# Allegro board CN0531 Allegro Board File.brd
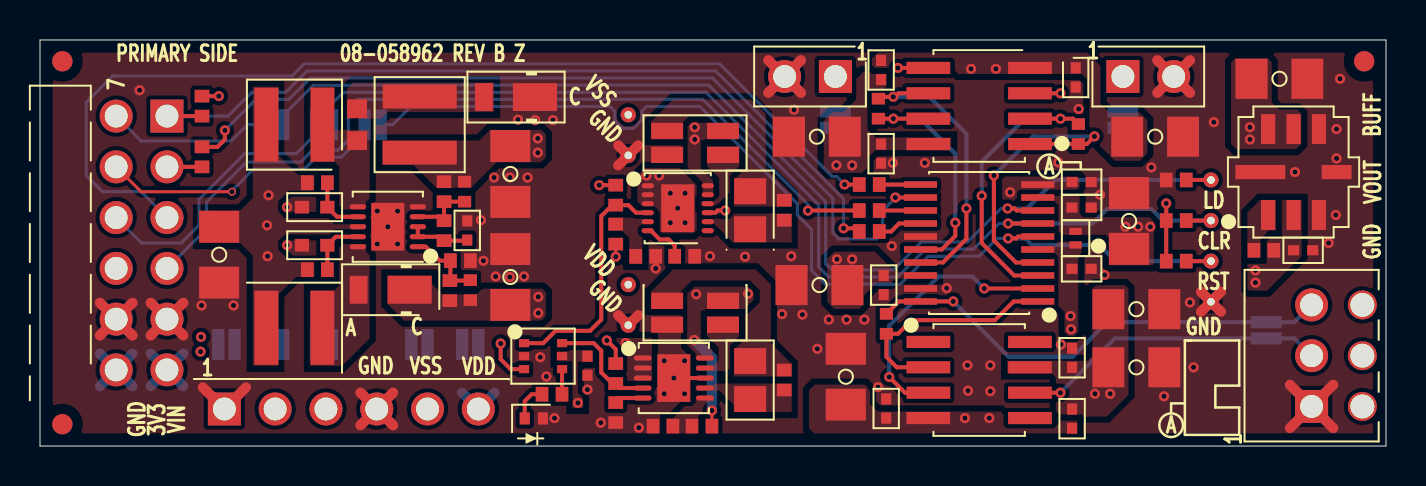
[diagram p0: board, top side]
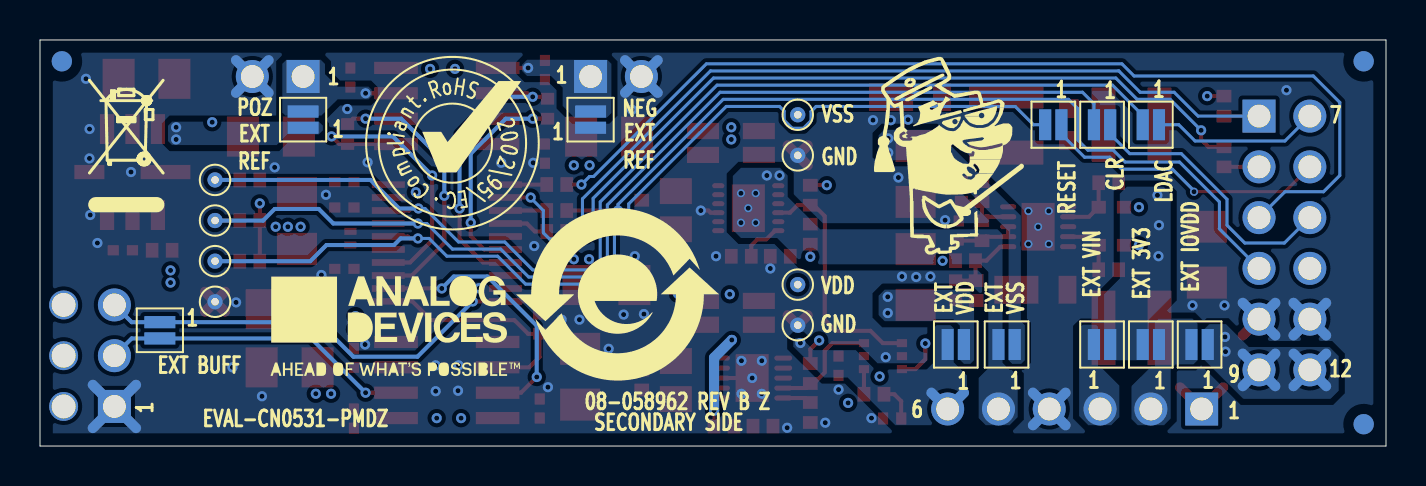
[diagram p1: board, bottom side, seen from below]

Outline 67.31 x 20.32 mm; copper layers: TOP, L2_GND, L3_PWR, BOTTOM. Coordinates in mm from the lower left corner of the outline.
Outline path: 0,20.32 0,0 67.31,0 67.31,20.32 0,20.32

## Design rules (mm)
constraint set DEFAULT: min track width 0.152

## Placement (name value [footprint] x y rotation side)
A1  AD8676BRZ  [SO8]  46.96 17.02 90 top
C1  4.7uF  [C1206_SP]  32.76 6.67 180 top
C2  4.7uF  [C1206_SP]  32.76 15.17 180 top
C3  0.1uF  [C0402H22]  27.38 4.02 90 top
C4  10uF  [C1206H71]  8.96 9.58 270 top
C5  0.1uF  [C0402H22]  63.16 9.8 180 top
C6  10uF  [C1206H71]  61.98 18.38 0 top
C7  10uF  [C1206H71]  38.85 15.48 0 top
C8  10uF  [C1206H71]  55.77 15.48 180 top
C9  0.47uF  [C0402_A]  13.73 10.05 180 top
C10  0.47uF  [C0402_A]  13.73 11.95 180 top
C11  0.1uF  [C0402H22]  42.06 14.63 90 top
C12  0.1uF  [C0402H22]  51.79 18.44 90 top
C13  0.1uF  [C0402H22]  42.06 18.82 90 top
C14  1uF  [C0603]  15.86 16.08 90 top
C15  220pF  [C0402]  51.93 15.61 270 top
C16  220pF  [C0402]  41.93 16.88 90 top
C17  33pF  [C0402]  21.52 7.8 90 top
C18  75pF  [C0402]  21.23 12.73 90 top
C19  4.7uF  [C1206H71]  23.52 8.46 90 top
C20  10uF  [C1206H71]  23.52 13.61 270 top
C21  0.1uF  [C0402H22]  21.37 10.79 90 top
C24  10uF  [C1206H71]  54.46 11.26 270 top
C25  0.1uF  [C0402H22]  52.09 11.94 180 top
C26  0.1uF  [C0402H22]  52.09 13.21 180 top
C27  0.1uF  [C0402H22]  42.19 8.06 270 top
C28  10uF  [C1206H71]  38.98 8.06 180 top
C29  10uF  [C1206H71]  54.83 6.85 0 top
C30  0.1uF  [C0402H22]  52.09 8.87 0 top
C31  10pF  [C0402]  42.33 6.12 270 top
C32  0.1uF  [C0402H22]  51.61 1.37 90 top
C33  0.1uF  [C0402H22]  42.32 1.88 90 top
C34  10uF  [C1206H71]  40.3 3.47 90 top
C35  10uF  [C1206H71]  54.83 3.94 0 top
C36  0.1uF  [C0402H22]  51.61 4.42 90 top
C37  4.7uF  [C0805H53]  35.51 3.3 90 top
C38  4.7uF  [C0805H53]  35.51 11.8 90 top
D1  DFLS120L-7  [POWERDI123]  17.54 7.82 180 top
D2  DFLS120L-7  [POWERDI123]  23.81 17.46 180 top
D3  BAT54LPS  [DFN2_1X0_6]  51.79 10.4 90 top
DS1  SML-P11MTT86RR  [LED0402]  24.7 1.38 180 top
L1  10UH  [LSMSQ157H71-2]  12.73 5.92 0 top
L2  15UH  [LSMSQ157H47_PS]  12.73 16.08 0 top
L3  15UH  [LSMSQ157H47_PS]  18.99 16.08 270 top
NOREF  -  []  67.3 20.32 180 top
NOREF#2  -  []  0 20.32 270 top
NOREF#3  -  []  40.61 255.22 0 top
NOREF#4  -  []  0 0 0 top
NOREF#5  -  []  103.86 66.62 0 top
NOREF#6  -  [unnamed#2]  1.12 19.25 0 top
NOREF#7  -  []  67.31 0 90 top
NOREF#8  -  []  33.88 33.1 0 top
NOREF#9  -  []  67.3 0 90 top
NOREF#10  -  [unnamed#2]  66.22 19.25 0 top
NOREF#11  -  []  3.81 3.81 0 top
NOREF#12  -  []  0 0 0 top
NOREF#13  -  []  28.3 180.8 270 top
NOREF#14  -  []  0 0 0 top
NOREF#15  -  []  -59.21 -127.81 0 top
NOREF#16  -  []  -59.33 -127.81 0 top
NOREF#17  -  []  103.48 -60.38 0 top
NOREF#18  -  []  56.87 139.01 0 top
NOREF#19  -  []  67.31 0 0 top
NOREF#20  -  []  0 20.32 0 top
NOREF#21  -  []  0 20.32 0 top
NOREF#22  -  [unnamed#2]  1.12 1.09 0 top
NOREF#23  -  []  3.81 3.81 0 top
NOREF#24  -  [unnamed#2]  1.12 19.25 180 bottom
NOREF#25  -  []  63.2 11.76 180 bottom
NOREF#26  -  []  21.86 14.53 180 bottom
NOREF#27  -  [unnamed#2]  1.12 1.09 180 bottom
NOREF#28  -  []  46.69 15.16 180 bottom
NOREF#29  -  [unnamed#2]  66.22 19.25 180 bottom
NOREF#30  -  []  49.84 5.97 180 bottom
NOREF#31  -  []  38.43 7.59 180 bottom
P1  TSW-106-07-G-S  [CNHDR1X6H330]  9.22 1.85 0 top
P2  TSW-106-25-F-D-RA  [CNHDRRA2X6H240]  6.35 16.51 270 top
P3  TSW-102-07-G-S  [CNTHMHDR1X2L200W98H343]  54.15 18.49 0 top
P4  TSW-102-07-G-S  [CNTHMHDR1X2L200W98H343]  39.78 18.49 180 top
P5  1725669  [CNTH1X3H335]  63.59 1.98 90 top
P6  -  [JPSLD02]  9.32 5.08 0 bottom
P7  -  [JPSLD02]  11.76 5.08 0 bottom
P8  -  [JPSLD02]  14.2 5.08 180 bottom
P9  -  [JPSLD02]  54.15 16.33 90 bottom
P10  -  [JPSLD02]  39.78 16.33 90 bottom
P11  -  [JPSLD02]  21.51 5.08 0 bottom
P12  -  [JPSLD02]  18.97 5.08 0 bottom
P13  -  [JPSLD02]  61.32 5.79 270 bottom
P14  -  [JPSLD02]  11.76 16.08 0 bottom
P15  -  [JPSLD02]  14.2 16.08 0 bottom
P16  -  [JPSLD02]  16.64 16.08 0 bottom
R1  10K  [R0402]  8.1 17.01 270 top
R2  10K  [R0402]  56.82 9.25 0 top
R3  10K  [R0402]  56.82 11.28 0 top
R4  120  [R0402]  25.61 2.59 180 top
R5  10K  [R0402]  56.82 13.32 180 top
R6  10K  [R0402]  61.2 9.8 180 top
R7  4.7K  [R0402]  13.87 8.82 0 top
R8  4.7K  [R0402]  13.87 13.18 0 top
R9  105K  [R0402]  20.5 7.78 90 top
R10  15K  [R0402]  21.03 9.28 0 top
R11  15K  [R0402]  20.21 10.78 90 top
R12  120K  [R0402]  20.21 12.73 90 top
R13  1MEG  [R0402]  33.1 1 180 top
R14  51K  [R0402]  31.15 1 180 top
R15  1MEG  [R0402]  28.79 10.6 90 top
R16  51K  [R0402]  30.29 9.5 0 top
R17  200K  [R0402]  28.79 3.63 90 top
R18  200K  [R0402]  28.79 12.55 270 top
R19  1.3K  [R0402]  28.79 1.68 270 top
R20  19.6K  [R0402]  32.24 9.5 0 top
R21  75K  [R0402]  37.22 3.3 90 top
R22  75K  [R0402]  37.22 11.8 90 top
R23  0  [R0402]  41.47 10.74 180 top
R24  0  [R0402]  41.47 13.09 180 top
R25  0  [R0402]  8.1 14.47 270 top
R26  0  [R0402]  41.47 11.79 180 top
TP1  TESTPAD  [TPC30D15]  58.56 7.22 0 top
TP2  TESTPAD  [TPC30D15]  58.56 13.32 0 top
TP3  TESTPAD  [TPC30D15]  58.56 11.28 0 top
TP4  TESTPAD  [TPC30D15]  58.56 9.25 0 top
TP5  TESTPAD  [TPC30D15]  29.42 8.08 0 top
TP6  TESTPAD  [TPC30D15]  29.42 16.58 0 top
TP7  TESTPAD  [TPC30D15]  29.42 6.05 0 top
TP8  TESTPAD  [TPC30D15]  29.42 14.54 0 top
U1  NC7SZ11P6X  [SC70-6]  25.16 4.5 270 top
U2  LTC6655BHLS8-5#PBF  [LCC8H61]  62.69 13.71 0 top
U3  LT3471EDD#PBF  [QFN10_3X3_PAD2_38X1_64]  17.39 10.97 90 top
U4  AD5791BRUZ  [TSSOP20]  46.96 10.16 90 top
U5  LT3093EDD#PBF  [DFN12_3X3_PAD2_38X1_65]  31.89 11.9 270 top
U6  LT3042EDD#PBF  [DFN10_3X3_PAD2_38X1_64]  31.7 3.4 270 top
U7  AD8675ARZ  [SO8]  46.96 3.3 270 top

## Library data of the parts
A1 = ADOPAMP2: Tolerance: N/A; User Part Number: UPN; alternate symbols: (); part number: ADOPAMP2_SM-AD8676BRZ,E011141,SO8; tolerance: N/A
C1 C2 = CAP_SP: User Part Number: UPN; Tolerance: 20; alternate symbols: (); part number: CAP_SP_SM-4.7UF,50V,20,E038838,C1206_SP; tolerance: 20
C3 C5 C11-C13 C21 C25-C27 C30 C32 C33 C36 = CAP: Tolerance: 10; User Part Number: UPN; alternate symbols: (); part number: CAP_SM-0.1UF,50V,10,E018452,C0402H22; tolerance: 10
C4 C6-C8 C20 C24 C28 C29 C34 C35 = CAP: Tolerance: 10; User Part Number: UPN; alternate symbols: (); part number: CAP_SM-10UF,50V,10,E026881,C1206H71; tolerance: 10
C9 C10 = CAP: Tolerance: 10; User Part Number: UPN; alternate symbols: (); part number: CAP_SM-0.47UF,50V,10,E020369,C0402_A; tolerance: 10
C14 = CAP: User Part Number: UPN; Tolerance: 10; alternate symbols: (); part number: CAP_SM-1UF,50V,10,E023087,C0603; tolerance: 10
C15 C16 = CAP: User Part Number: UPN; Tolerance: 5; alternate symbols: (); part number: CAP_SM-220PF,50V,5,E018153,C0402; tolerance: 5
C17 = CAP: User Part Number: UPN; Tolerance: 5; alternate symbols: (); part number: CAP_SM-33PF,50V,5,E027128,C0402; tolerance: 5
C18 = CAP: User Part Number: UPN; Tolerance: 5; alternate symbols: (); part number: CAP_SM-75PF,50V,5,E033948,C0402; tolerance: 5
C19 = CAP: Tolerance: 20; User Part Number: UPN; alternate symbols: (); part number: CAP_SM-4.7UF,50V,20,E028522,C1206H71; tolerance: 20
C31 = CAP: User Part Number: UPN; Tolerance: 5; alternate symbols: (); part number: CAP_SM-10PF,50V,5,E035301,C0402; tolerance: 5
C37 C38 = CAP: Tolerance: 10; User Part Number: UPN; alternate symbols: (); part number: CAP_SM-4.7UF,25V,10,E025752,C0805H53; tolerance: 10
D1 D2 = DIOSCHOTTKY: User Part Number: UPN; Tolerance: N/A; alternate symbols: (); part number: DIOSCHOTTKY_SM-DFLS120L-7,20V,N/A,E033687,POWERDI123; tolerance: N/A
D3 = DIOSCHOTTKY: Tolerance: N/A; User Part Number: UPN; alternate symbols: (); part number: DIOSCHOTTKY_SM-BAT54LPS,30V,N/A,E023691,DFN2_1X0_6; tolerance: N/A
DS1 = DIOLED: User Part Number: UPN; Tolerance: N/A; alternate symbols: (); part number: DIOLED_SM-SML-P11MTT86R,N/A,N/A,E014445,LED0402; tolerance: N/A
L1 = IND: User Part Number: UPN; Tolerance: 20; alternate symbols: (); part number: IND_SM-10UH,20,E032200,LSMSQ157H71-2; tolerance: 20
L2 L3 = IND: User Part Number: UPN; Tolerance: 20; alternate symbols: (); part number: IND_SM-15UH,20,E032207,LSMSQ157H47_PS; tolerance: 20
P1 = CN6P: Tolerance: N/A; User Part Number: UPN; alternate symbols: (); part number: CN6P_TH-TSW-106-07-G-S,E026233,CNHDR1X6H330; tolerance: N/A
P2 = CN12P_V3: User Part Number: UPN; Tolerance: N/A; alternate symbols: (); part number: CN12P_V3_TH-TSW-106-25-F-D-RA,E018495,CNHDRRA2X6H240; tolerance: N/A
P3 P4 = CN2P: User Part Number: UPN; Tolerance: N/A; alternate symbols: (); part number: CN2P_TH-TSW-102-07-G-S,E031850,CNTHMHDR1X2L200W98H343; tolerance: N/A
P5 = CN3P: Tolerance: N/A; User Part Number: UPN; alternate symbols: (); part number: CN3P_TH-1725669,E019899,CNTH1X3H335; tolerance: N/A
P6-P16 = NC2P: User Part Number: UPN; Tolerance: N/A; alternate symbols: (); part number: NC2P_SM-JPSLD02,E006230,JPSLD02; tolerance: N/A
R1-R3 R5 R6 = RES: User Part Number: UPN; Tolerance: 1; alternate symbols: (R0402L,R0402L_ALT); part number: RES_SM-10K,E003751,1/10W,1,R0402; tolerance: 1
R4 = RES: User Part Number: UPN; Tolerance: 5; alternate symbols: (R0402L); part number: RES_SM-120,E003453,1/10W,5,R0402; tolerance: 5
R7 R8 = RES: User Part Number: UPN; Tolerance: 1; alternate symbols: (R0402L,R0402L_ALT); part number: RES_SM-4.7K,E008190,1/10W,1,R0402; tolerance: 1
R9 = RES: User Part Number: UPN; Tolerance: 1; alternate symbols: (R0402L); part number: RES_SM-105K,E019614,1/16W,1,R0402; tolerance: 1
R10 R11 = RES: User Part Number: UPN; Tolerance: 1; alternate symbols: (R0402L); part number: RES_SM-15K,E007441,1/10W,1,R0402; tolerance: 1
R12 = RES: User Part Number: UPN; Tolerance: 1; alternate symbols: (R0402L); part number: RES_SM-120K,E015615,1/10W,1,R0402; tolerance: 1
R13 R15 = RES: User Part Number: UPN; Tolerance: 1; alternate symbols: (R0402L); part number: RES_SM-1MEG,E003749,1/10W,1,R0402; tolerance: 1
R14 R16 = RES: User Part Number: UPN; Tolerance: 1; alternate symbols: (R0402L,R0402L_ALT); part number: RES_SM-51K,E013080,1/10W,1,R0402; tolerance: 1
R17 R18 = RES: User Part Number: UPN; Tolerance: 1; alternate symbols: (R0402L); part number: RES_SM-200K,E004033,1/10W,1,R0402; tolerance: 1
R19 = RES: User Part Number: UPN; Tolerance: 1; alternate symbols: (R0402L,R0402L_ALT); part number: RES_SM-1.3K,E015613,1/10W,1,R0402; tolerance: 1
R20 = RES: User Part Number: UPN; Tolerance: 1; alternate symbols: (R0402L); part number: RES_SM-19.6K,E027321,1/10W,1,R0402; tolerance: 1
R21 R22 = RES: User Part Number: UPN; Tolerance: 1; alternate symbols: (R0402L,R0402L_ALT); part number: RES_SM-75K,E011153,1/10W,1,R0402; tolerance: 1
R23-R26 = RES: User Part Number: UPN; Tolerance: JUMPER; alternate symbols: (R0402L,R0402L_ALT); part number: RES_SM-0,E003438,1/10W,JUMPER,R0402; tolerance: JUMPER
TP1-TP8 = NCTESTPAD: Tolerance: N/A; User Part Number: UPN; alternate symbols: (); part number: NCTESTPAD_TH-TESTPAD,E013464,TPC30D15; tolerance: N/A
U1 = ICNC7SZ11X6X: Tolerance: N/A; User Part Number: UPN; alternate symbols: (); part number: ICNC7SZ11X6X_SM-NC7SZ11P6X,E022115,SC70-6; tolerance: N/A
U2 = LINLTC6655_V2: User Part Number: UPN; Tolerance: N/A; alternate symbols: (); part number: LINLTC6655_V2_SM-LTC6655BHLS8-5#PBF,E030760,LCC8H61; tolerance: N/A
U3 = LINLT3471: User Part Number: UPN; Tolerance: N/A; alternate symbols: (); part number: LINLT3471_SM-LT3471EDD#PBF,E030330,QFN10_3X3_PAD2_38X1_64; tolerance: N/A
U4 = AD5791: Tolerance: N/A; User Part Number: UPN; alternate symbols: (); part number: AD5791_SM-AD5791BRUZ,E011635,TSSOP20; tolerance: N/A
U5 = ADLT3093: User Part Number: UPN; Tolerance: N/A; alternate symbols: (); part number: ADLT3093_SM-LT3093EDD#PBF,E038442,DFN12_3X3_PAD2_38X1_65; tolerance: N/A
U6 = LINLT3042: Tolerance: N/A; User Part Number: UPN; alternate symbols: (); part number: LINLT3042_SM-LT3042EDD#PBF,E029807,DFN10_3X3_PAD2_38X1_64; tolerance: N/A
U7 = AD8675: Tolerance: N/A; User Part Number: UPN; alternate symbols: (); part number: AD8675_SM-AD8675ARZ,E005913,SO8; tolerance: N/A

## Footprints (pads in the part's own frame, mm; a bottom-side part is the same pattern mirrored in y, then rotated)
C0402
  rect 0.584x0.66 smd: 1(-0.5,0) 2(0.5,0)
C0402_A
  rect 0.711x0.635 smd: 1(-0.635,0) 2(0.635,0)
C0402H22
  rect 0.559x0.508 smd: 1(-0.479,0) 2(0.479,0)
C0603
  rect 0.94x0.991 smd: 1(-0.8,0) 2(0.8,0)
C0805H53
  rect 1.295x1.6 smd: 1(-0.953,0) 2(0.953,0)
C1206_SP
  rect 1.6x0.813 smd: 1(-1.397,-0.597) 2(1.397,-0.597) 3(1.397,0.597) 4(-1.397,0.597)
C1206H71
  rect 1.6x2.007 smd: 1(-1.397,0) 2(1.397,0)
CNHDR1X6H330
  rect 1.651x1.651 hole 1.143: 1(0,0)
  round 1.651 hole 1.143: 2(2.54,0) 3(5.08,0) 4(7.62,0) 5(10.16,0) 6(12.7,0)
CNHDRRA2X6H240
  rect 1.651x1.651 hole 1.143: 1(0,0)
  round 1.651 hole 1.143: 2(2.54,0) 3(5.08,0) 4(7.62,0) 5(10.16,0) 6(12.7,0) 7(0,-2.54) 8(2.54,-2.54) 9(5.08,-2.54) 10(7.62,-2.54) 11(10.16,-2.54) 12(12.7,-2.54)
CNTH1X3H335
  round 1.448 hole 1.194 unplated: (0,-2.54) (2.54,-2.54) (5.08,-2.54)
  rect 1.651x1.651 hole 1.143: 1(0,0)
  round 1.651 hole 1.143: 2(2.54,0) 3(5.08,0)
CNTHMHDR1X2L200W98H343
  rect 1.651x1.651 hole 1.143: 1(0,0)
  round 1.651 hole 1.143: 2(2.54,0)
DFN2_1X0_6
  rect 0.356x0.61 smd: A(0.34,0) C(-0.34,0)
DFN10_3X3_PAD2_38X1_64
  oval 0.254x0.889 smd: 1(-1,-1.555) 2(-0.5,-1.555) 3(0,-1.555) 4(0.5,-1.555) 5(1,-1.555) 6(1,1.555) 7(0.5,1.555) 8(0,1.555) 9(-0.5,1.555) 10(-1,1.555)
  rect 2.388x1.651 smd: PAD(0,0)
DFN12_3X3_PAD2_38X1_65
  oval 0.254x0.61 smd: 1(-1.125,-1.5) 2(-0.675,-1.5) 3(-0.225,-1.5) 4(0.225,-1.5) 5(0.675,-1.5) 6(1.125,-1.5) 7(1.125,1.5) 8(0.675,1.5) 9(0.225,1.5) 10(-0.225,1.5) 11(-0.675,1.5) 12(-1.125,1.5)
  rect 2.388x1.651 smd: PAD(0,0)
JPSLD02
  rect 0.61x1.549 smd: 1(-0.406,0) 2(0.406,0)
LCC8H61
  rect 0.711x1.499 smd: 1(-1.27,-2.151) 2(0,-2.151) 3(1.27,-2.151) 5(1.27,2.151) 6(0,2.151) 7(-1.27,2.151)
  rect 1.499x0.711 smd: 4(2.151,0)
  rect 2.489x0.711 smd: 8(-1.655,0)
LED0402
  rect 0.508x0.61 smd: A(0.454,0) C(-0.454,0)
LSMSQ157H47_PS
  rect 1.194x3.708 smd: 1(-1.4,0) 2(1.4,0)
LSMSQ157H71-2
  rect 1.194x3.708 smd: 1(-1.4,0) 2(1.4,0)
POWERDI123
  rect 0.889x1.397 smd: A(1.606,0)
  rect 2.21x1.397 smd: C(-0.945,0)
QFN10_3X3_PAD2_38X1_64
  oval 0.254x0.813 smd: 1(-1,-1.5) 2(-0.5,-1.5) 3(0,-1.5) 4(0.5,-1.5) 5(1,-1.5) 6(1,1.5) 7(0.5,1.5) 8(0,1.5) 9(-0.5,1.5) 10(-1,1.5)
  rect 2.388x1.651 smd: PAD(0,0)
R0402
  rect 0.635x0.737 smd: 1(-0.5,0) 2(0.5,0)
SC70-6
  rect 0.406x0.508 smd: 1(-0.65,-0.95) 2(0,-0.95) 3(0.65,-0.95) 4(0.65,0.95) 5(0,0.95) 6(-0.65,0.95)
SO8
  rect 0.61x2.184 smd: 1(-1.905,-2.54) 2(-0.635,-2.54) 3(0.635,-2.54) 4(1.905,-2.54) 5(1.905,2.54) 6(0.635,2.54) 7(-0.635,2.54) 8(-1.905,2.54)
TPC30D15
  round 0.762 hole 0.381: 1(0,0)
TSSOP20
  rect 0.33x1.651 smd: 1(-2.925,-2.93) 2(-2.275,-2.93) 3(-1.625,-2.93) 4(-0.975,-2.93) 5(-0.325,-2.93) 6(0.325,-2.93) 7(0.975,-2.93) 8(1.625,-2.93) 9(2.275,-2.93) 10(2.925,-2.93) 11(2.925,2.93) 12(2.275,2.93) 13(1.625,2.93) 14(0.975,2.93) 15(0.325,2.93) 16(-0.325,2.93) 17(-0.975,2.93) 18(-1.625,2.93) 19(-2.275,2.93) 20(-2.925,2.93)
unnamed#2
  round 1.016 smd: (0,0)

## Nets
3V3: C3.2(N2) C24.2(N2) C25.2(N2) D3.A(P) P1.2 P6.2(N2) P7.1 U1.5 U4.9
AGND: C1.3 C2.3 C3.1 C4.2(N2) C5.1 C6.2(N2) C7.1 C8.1 C9.2(N2) C10.2(N2) C11.1 C12.1 C19.2(N2) C20.2(N2) C21.2(N2) C24.1 C25.1 C26.1 C27.2(N2) C28.2(N2) C29.2(N2) C30.2(N2) C33.2(N2) C34.2(N2) C35.2(N2) C36.2(N2) D2.C DS1.C P1.1 P1.4 P2.5 P2.11 P3.2(N2) P4.2(N2) P5.1 P10.1 R5.2(N2) R10.2(N2) R14.2(N2) R16.2(N2) R19.2(N2) R20.2(N2) TP1.1(N1) TP7.1(N1) TP8.1(N1) U1.2 U2.3 U2.4 U2.5 U2.8 U3.5 U3.PAD U4.15 U4.19 U5.9 U6.8 U6.PAD
VDD: A1.8 C1.1 C5.2(N2) C7.2(N2) C11.2(N2) C13.1 C29.1 C30.1 C32.2(N2) C35.1 C36.1 D3.C R6.1 R13.1 TP5.1(N1) U2.2 U4.5 U6.10 U7.7
VIN: C4.1 L1.1 L2.1 P7.2(N2) P8.2(N2) R7.1 R8.1 U3.8
VSS: A1.4(V-) C2.1 C8.2(N2) C12.2(N2) C13.2(N2) C27.1 C28.1 C32.1 C33.1 C34.1 R15.1 TP6.1(N1) U4.18(VSS) U5.11 U5.12 U7.4(V-)
CLR_N: P15.2(N2) R3.2(N2) TP3.1(N1) U4.7
DAC_INV: C31.2(N2) U4.1 U7.2
DAC_RFB: C31.1 P5.3(N3) P13.1 U4.20
DAC_VOUT: U4.2 U7.3
FB_VNEG: C18.1 R11.2(N2) R12.1 U3.4
FB_VPOS: C17.2(N2) R9.2(N2) R10.1 U3.1
IOVCC: C26.2(N2) P2.6 P2.12(VCC2) P6.1 R1.1 R2.1 R3.1 R17.2(N2) R18.1 U1.3 U4.10
LDAC_N: P14.2(N2) R5.1 TP2.1(N1) U4.8
NEG_8_VSS: C18.2(N2) C20.1 L3.2(N2) P12.1 R12.2(N2)
NEG_EX_REF: A1.5 P4.1 P10.2(N2)
NEG_SET: C38.1 R22.1 U5.8
NEG_VSS: P1.5 P12.2(N2) U5.1 U5.2 U5.3 U5.PAD
PG_VNEG: R18.2(N2) U1.1 U5.4
PG_VPOZ: R17.1 U1.6 U6.4
PGFB_VNEG: R15.2(N2) R16.1 U5.5
PGFB_VPOZ: R13.2(N2) R14.1 U6.6
POZ_8_VDD: C17.1 C19.1 D1.C P11.1 R9.1
POZ_EX_REF: A1.3 P3.1 P9.2(N2)
POZ_SET: C37.1 R21.1 U6.7(SET)
POZ_VDD: P1.6(N6) P11.2(N2) U6.1 U6.2 U6.3
RESET_N: P16.2(N2) R2.2(N2) TP4.1(N1) U4.6
SCLK: R26.1 U4.13
SDIN: R25.1 U4.12
SDO: R24.1 U4.11
SENSE_VDD: C1.4(N4) U6.9
SENSE_VSS: C2.4(N4) U5.10
SYNC_N: R23.1 U4.14
UNNAMED_4_AD8675_I108_OUT: P5.2 P13.2(N2) U7.6
UNNAMED_4_ADLT3093_I191_ILIM: R20.1 U5.6
UNNAMED_4_CAP_I23_N1: C10.1 R8.2(N2) U3.7
UNNAMED_4_CAP_I25_N1: C9.1 R7.2(N2) U3.9
UNNAMED_4_CAP_I36_N1: C6.1 P9.1 U2.6(VOUT_S) U2.7
UNNAMED_4_CAP_I74_N1: C21.1 R11.1 U3.2 U3.3(VREF)
UNNAMED_4_CAP_I132_N2: C1.2 C37.2(N2) R21.2(N2)
UNNAMED_4_CAP_I152_N1: C14.1 L2.2(N2) U3.6
UNNAMED_4_CAP_I152_N2: C14.2(N2) D2.A(P) L3.1
UNNAMED_4_CAP_I197_N2: C2.2 C38.2(N2) R22.2(N2)
UNNAMED_4_CN12PV3_I234_P1: P2.1 R1.2(N2) R23.2(N2)
UNNAMED_4_CN12PV3_I234_P2: P2.2 R25.2(N2)
UNNAMED_4_CN12PV3_I234_P3: P2.3 R24.2(N2)
UNNAMED_4_CN12PV3_I234_P4: P2.4 R26.2(N2)
UNNAMED_4_CN12PV3_I234_P7: P2.7 P14.1
UNNAMED_4_CN12PV3_I234_P8: P2.8 P16.1
UNNAMED_4_CN12PV3_I234_P9: P2.9 P15.1
UNNAMED_4_DIOLED_I200_P: DS1.A(P) R4.2(N2)
UNNAMED_4_DIOSCHOTTKY_I78_P: D1.A(P) L1.2(N2) U3.10
UNNAMED_4_ICNC7SZ11X6X_I204_Y: R4.1 U1.4(Y)
UNNAMED_4_LINLT3042_I105_ILIM: R19.1 U6.5
UNNAMED_4_LINLTC6655V2_I268_SHD: R6.2(N2) U2.1
V_EXT: P1.3 P8.1
V_REFN_F: A1.7 C16.1 U4.16
V_REFN_S: A1.6 C16.2(N2) U4.17
V_REFP_F: A1.1 C15.2(N2) U4.4
V_REFP_S: A1.2 C15.1 U4.3

Pads without a net: P2 10; U5 7; U7 1 5 8

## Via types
v1: diameter 0.406, hole 0.254, TOP to BOTTOM, 11 vias
v2: diameter 0.508, hole 0.254, TOP to BOTTOM, 131 vias

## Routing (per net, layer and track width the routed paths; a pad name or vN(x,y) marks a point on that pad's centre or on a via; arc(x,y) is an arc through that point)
3V3: length 2.3
  L3_PWR w0.508: 10.95,2.67 P1.2 12.57,2.67
  vias: v2(26.9,2.16) v2(54.28,10.97) v2(54.91,10.97) v2(55.52,10.97)
AGND: length 109
  TOP w0.203: U5.9 33.77,11.68 33.88,11.79 v2(34.26,11.79) ; R16.2 v2(30.79,8.88) ; U6.8 v2(31.7,3.4)
  TOP w0.508: P5.1 64.67,3.06 ; P5.1 62.51,0.9 ; P5.1 64.67,0.9 ; P5.1 62.51,3.06 ; 55.88,19.31 P3.2 ; P3.2 55.88,17.68 ; P3.2 57.51,17.68 ; P3.2 57.51,19.31 ; 8.14,2.93 P1.1 10.3,2.93 ; P1.4 17.65,2.67 ; P1.4 16.03,1.04 ; P1.4 17.65,1.04 ; P1.4 16.03,2.67 ; 3,7.16 P2.11 ; P2.11 4.62,7.16 ; P2.11 4.62,5.54 ; P2.11 3,5.54 ; TP1.1 59.06,7.72 ; TP1.1 58.06,7.72 ; TP1.1 59.06,6.72 ; TP1.1 58.06,6.72 ; 28.92,6.55 TP7.1 29.92,6.55 ; 5.54,7.16 P2.5 ; P2.5 7.16,7.16 ; P2.5 5.54,5.54 ; P2.5 7.16,5.54 ; TP8.1 29.92,15.04 ; TP8.1 28.92,15.04 ; TP8.1 28.92,14.04 ; P4.2 38.05,19.31 ; P4.2 36.42,19.31 ; P4.2 38.05,17.68 ; P4.2 36.42,17.68
  L2_GND w0.508: 58.06,7.72 TP1.1 ; TP1.1 59.06,6.72 ; TP1.1 59.06,7.72 ; TP1.1 58.06,6.72 ; 8.41,2.67 P1.1 ; P1.1 10.03,1.04 ; P1.1 8.41,1.04 ; P1.1 10.03,2.67 ; P3.2 57.51,17.68 ; P3.2 55.88,17.68 ; P3.2 57.51,19.31 ; P3.2 55.88,19.31 ; P1.4 17.65,1.04 ; P1.4 16.03,2.67 ; P1.4 17.65,2.67 ; P1.4 16.03,1.04 ; 3,7.16 P2.11 ; P2.11 4.62,7.16 ; P2.11 4.62,5.54 ; P2.11 3,5.54 ; 62.77,2.8 P5.1 ; P5.1 64.4,1.17 ; P5.1 64.4,2.8 ; P5.1 62.77,1.17 ; TP8.1 29.92,15.04 ; TP8.1 28.92,15.04 ; TP8.1 28.92,14.04 ; 5.54,7.16 P2.5 ; P2.5 5.54,5.54 ; P2.5 7.16,5.54 ; P2.5 7.16,7.16 ; TP7.1 29.92,5.55 ; TP7.1 28.92,6.55 ; TP7.1 29.92,6.55 ; 36.42,17.68 P4.2 ; P4.2 38.05,17.68 ; P4.2 36.42,19.31 ; P4.2 38.05,19.31
  BOTTOM w0.508: 55.88,17.68 P3.2 ; P3.2 55.88,19.31 ; P3.2 57.51,19.31 ; P3.2 57.51,17.68 ; 5.54,5.54 P2.5 ; P2.5 7.16,7.16 ; P2.5 5.54,7.16 ; P4.2 38.05,19.31 ; P4.2 38.05,17.68 ; P4.2 36.42,17.68 ; P4.2 36.42,19.31 ; P2.11 4.62,7.16 ; P2.11 3,7.16 ; P2.11 3,5.54 ; P2.11 4.62,5.54 ; 16.03,1.04 P1.4 ; P1.4 16.03,2.67 ; P1.4 17.65,2.67 ; P1.4 17.65,1.04 ; P5.1 64.67,0.9 ; P5.1 62.51,0.9 ; P5.1 62.51,3.06 ; P5.1 64.67,3.06
  vias: v1(16.87,11.76) v1(16.87,10.11) v1(17.39,10.97) v1(17.88,11.76) v1(17.88,10.11) v2(4.98,17.81) v2(8.08,7.04) v2(9.68,7.04) v2(12.36,11.95) v2(12.36,10.05) v2(22.05,11.3) v2(22.17,9.27) v2(22.71,13.44) v2(22.78,8.48) v2(23.49,13.44) v2(23.49,8.46) v2(23.9,16.33) v2(24.21,8.48) v2(24.38,13.44) v2(24.76,16.31) v2(25.02,4.45) v2(25.32,3.48) v2(25.65,16.31) v2(25.73,1.4) v2(27.38,2.82) v2(28.04,1.17) v2(29.95,0.91) v2(31.22,4.27) v2(31.22,2.62) v2(32.23,4.27) v2(32.23,2.62) v2(33.5,9.5) v2(35.26,9.47) v2(37.11,6.6) v2(37.57,9.5) v2(37.71,16.83) v2(38.13,6.58) v2(38.87,4.87) v2(39.45,6.32) v2(40.34,6.32) v2(41.22,6.32) v2(41.91,2.95) v2(42.65,14.17) v2(42.6,10.01) v2(44.25,14.17) v2(45.34,7.9) v2(46.38,4.04) v2(46.41,2.77) v2(47.52,4.04) v2(47.52,2.74) v2(50.93,14.2) v2(51.05,5.08) v2(51.94,16.87) v2(53.01,12.57) v2(53.24,8.56) v2(55.58,13.94) v2(56.21,2.49) v2(57.51,7.19) v2(57.69,3.94) v2(58.7,16.21) v2(62.76,13.71) v2(64.44,10.16) v2(64.83,15.86) v2(64.84,14.39) v2(64.8,11.56) v2(65.01,18.38)
VDD: length 4.7
  TOP w0.152: R13.1 v2(33.6,1.78)
  BOTTOM w0.508: v2(32.72,5.31) 33.6,4.42 v2(33.6,1.78)
  vias: v2(32.82,7.59) v2(35.41,7.62) v2(39.83,14.05) v2(40.61,14.05) v2(51.54,6.5) v2(51.56,5.84) v2(52.76,2.62) v2(53.52,2.62) v2(60.78,8.79) v2(60.78,8.18)
VIN:
  vias: v2(11.35,11.05) v2(11.43,12.55) v2(11.38,9.5)
VSS: length 0.6
  TOP w0.152: R15.1 v2(28.79,9.47)
  vias: v2(32.74,15.95) v2(32.74,15.34) v2(39.85,9.35) v2(40.61,9.35) v2(46.25,1.4) v2(46.56,18.87) v2(47.47,1.4) v2(47.8,18.87)
CLR_N: length 55.3
  TOP w0.203: U4.7 v2(48.41,11.14) ; R3.2 TP3.1
  BOTTOM w0.152: v2(48.41,11.14) 47.97,11.14 46.69,9.86 44.27,9.86 42.88,8.46 39.45,8.46 38.94,8.97 38.94,12.07 33.3,17.7 15.18,17.7 14.61,17.13 P15.2
  BOTTOM w0.203: TP3.1 56.15,11.28 55.58,11.86 53.37,11.86 52.64,11.14 v2(48.41,11.14)
DAC_INV: length 11.7
  TOP w0.203: U7.2 42.85,3.94 42.33,4.46 C31.2 42.91,5.62 43.59,6.3 47.75,6.3 48.69,7.23 U4.1
DAC_RFB: length 23.7
  TOP w0.203: v2(45.67,7.23) U4.20 42.94,7.23 C31.1
  BOTTOM w0.203: P5.3 62.73,6.2 P13.1 53.37,6.2 51.64,4.47 48.43,4.47 v2(45.67,7.23)
DAC_VOUT: length 13.5
  TOP w0.203: v2(47.22,7.88) U4.2 ; U7.3 43.25,2.67 v2(42.47,3.45)
  BOTTOM w0.203: v2(47.22,7.88) 46.62,8.48 44.93,8.48 42.47,6.02 v2(42.47,3.45)
FB_VNEG: length 3.4
  TOP w0.203: C18.1 R12.1 R11.2 20.01,11.47 U3.4
FB_VPOS: length 4
  TOP w0.203: U3.1 19.29,9.97 19.99,9.28 R10.1 20.53,8.31 R9.2 21.5,8.28 C17.2
IOVCC: length 26.5
  TOP w0.203: R1.1 v2(8.94,17.51) ; v2(56.32,12.14) R3.1 R2.1 ; R17.2 28.79,4.84 v2(28.35,5.28) ; v2(23.04,5.13) 23.04,4.34 23.53,3.85 U1.3 ; R18.1 v2(27.97,13.05)
  L3_PWR w0.508: 3,4.62 P2.12 ; P2.12 4.62,4.62 ; P2.12 4.62,3 ; P2.12 3,3 ; P2.6 7.16,3 ; P2.6 7.16,4.62 ; P2.6 5.54,3 ; P2.6 5.54,4.62
  BOTTOM w0.508: 5.54,3 P2.6 ; P2.6 5.54,4.62 ; P2.6 7.16,3 ; P2.6 7.16,4.62 ; P2.12 4.62,4.62 ; P2.12 3,3 ; P2.12 4.62,3 ; P2.12 3,4.62
  vias: v2(8.05,5.46) v2(8.03,4.72) v2(48.51,12.7)
LDAC_N: length 57.8
  TOP w0.203: U4.8 48.84,11.79 48.74,11.89 v2(48.39,11.89) ; R5.1 TP2.1
  BOTTOM w0.152: v2(48.39,11.89) 48.06,11.89 46.38,10.21 44.07,10.21 42.67,8.81 39.6,8.81 39.29,9.12 39.29,12.22 33.45,18.06 13.68,18.06 12.17,16.55 P14.2
  BOTTOM w0.203: v2(48.39,11.89) 49.35,11.89 50.78,13.32 TP2.1
NEG_8_VSS:
  vias: v2(24.89,15.39) v2(24.89,14.68)
NEG_EX_REF: length 1.5
  TOP w0.203: A1.5 v2(42.9,18.92)
NEG_VSS:
  vias: v1(31.52,12.65) v1(31.52,11.18) v1(31.89,11.9) v1(32.26,12.65) v1(32.26,11.18) v2(30.33,13.54) v2(30.96,13.54)
PG_VNEG: length 12.2
  TOP w0.203: U1.1 25.16,5.15 25.78,5.77 27.51,5.77 28.07,6.32 28.07,11.51 28.61,12.05 R18.2 29.43,12.05 29.8,11.68 U5.4
PG_VPOZ: length 5.6
  TOP w0.203: U6.4 29.01,2.9 R17.1 28.62,3.13 28.07,3.68 28.07,4.77 27.69,5.15 U1.6
POZ_8_VDD:
  vias: v2(24.92,7.47) v2(24.92,6.65)
POZ_EX_REF: length 1.5
  TOP w0.203: A1.3 v2(51.03,17.65)
POZ_VDD: length 2.3
  BOTTOM w0.508: 21.11,2.67 P1.6 22.73,2.67
  vias: v2(29.29,5.16)
RESET_N: length 52.7
  TOP w0.203: R2.2 TP4.1 ; U4.6 48.92,10.49 48.82,10.39 v2(48.41,10.39)
  BOTTOM w0.152: P16.2 17.63,16.08 18.54,16.99 28.5,16.99 28.75,16.74 28.75,16.28 29.13,15.9 29.69,15.9 30.1,16.31 30.1,16.76 30.33,16.99 32.99,16.99 37.87,12.12 37.87,11.56 38.58,10.85 38.58,8.79 39.27,8.1 43.03,8.1 44.42,9.5 46.96,9.5 47.85,10.39 v2(48.41,10.39)
  BOTTOM w0.203: TP4.1 53.79,9.25 52.98,10.06 49.61,10.06 49.28,10.39 v2(48.41,10.39)
SCLK: length 2.1
  TOP w0.203: U4.13 R26.1
SDIN: length 43.5
  TOP w0.203: R25.1 8.87,14.97 9.25,15.34 v2(9.25,15.8) ; U4.12 v2(42.77,12.44)
  BOTTOM w0.152: v2(42.77,12.44) 42.77,12.42 42.14,11.79 42.14,10.67 41.83,10.36 39.95,10.36 39.65,10.67 39.65,12.4 33.63,18.41 13.51,18.41 12.45,17.35 10.79,17.35 v2(9.25,15.8)
SDO: length 2.1
  TOP w0.203: U4.11 R24.1
SYNC_N: length 2.2
  TOP w0.203: R23.1 42.56,10.74 42.96,11.14 U4.14
UNNAMED_4_AD8675_I108_OUT: length 15.6
  TOP w0.203: U7.6 v2(51.03,2.67)
  BOTTOM w0.203: v2(51.03,2.67) 53.74,5.38 P13.2 62.73,5.38 P5.2
UNNAMED_4_ADLT3093_I191_ILIM: length 2.2
  TOP w0.203: R20.1 31.74,10.03 31.44,10.34 30.99,10.34 30.55,10.78 U5.6
UNNAMED_4_CAP_I23_N1: length 2.9
  TOP w0.203: R8.2 C10.1 14.85,11.47 U3.7
UNNAMED_4_CAP_I25_N1: length 2.9
  TOP w0.203: U3.9 14.79,10.47 C9.1 R7.2
UNNAMED_4_CAP_I36_N1:
  vias: v2(60.5,15.95) v2(60.5,15.34)
UNNAMED_4_CAP_I74_N1: length 3.1
  TOP w0.203: C21.1 21.33,10.28 R11.1 20.01,10.47 U3.2 U3.3
UNNAMED_4_CN12PV3_I234_P1: length 41.5
  TOP w0.203: P2.1 R1.2 ; R23.2 40.81,10.9 v2(40.18,10.9)
  BOTTOM w0.152: v2(40.18,10.9) 40.18,12.37 33.78,18.77 13.36,18.77 12.29,17.7 10.59,17.7 9.4,16.51 P2.1
UNNAMED_4_CN12PV3_I234_P2: length 1.8
  TOP w0.203: P2.2 R25.2
UNNAMED_4_CN12PV3_I234_P3: length 50.5
  TOP w0.203: v2(40.23,13.09) R24.2
  BOTTOM w0.152: P2.3 5.05,12.73 3.12,12.73 2.31,13.54 2.31,17.2 3.63,18.52 12.6,18.52 13.21,19.13 33.99,19.13 39.62,13.49 39.83,13.49 v2(40.23,13.09)
UNNAMED_4_CN12PV3_I234_P4: length 42.3
  TOP w0.203: v2(38.4,11.79) R26.2
  BOTTOM w0.152: P2.4 8.33,10.87 8.33,12.22 10.33,14.21 13.04,14.21 13.64,14.81 14.91,14.81 15.42,15.32 15.42,16.89 15.88,17.35 33.15,17.35 38.4,12.09 v2(38.4,11.79)
UNNAMED_4_CN12PV3_I234_P7: length 8.4
  BOTTOM w0.152: P14.1 10.36,16.08 9.55,15.27 5.05,15.27 P2.7
UNNAMED_4_CN12PV3_I234_P8: length 14.6
  TOP w0.152: v1(9.6,12.73) 5.05,12.73 P2.8
  BOTTOM w0.152: v1(9.6,12.73) 9.6,12.78 10.68,13.86 13.22,13.86 13.82,14.45 15.07,14.45 16.23,15.61 P16.1
UNNAMED_4_CN12PV3_I234_P9: length 14
  BOTTOM w0.152: P2.9 5.08,10.16 7.06,10.16 7.95,11.05 7.95,12.34 10.24,14.63 12.81,14.63 13.79,15.61 P15.1
UNNAMED_4_DIOLED_I200_P: length 1.9
  TOP w0.203: R4.2 24.59,2.59 24.24,2.25 DS1.A
UNNAMED_4_ICNC7SZ11X6X_I204_Y: length 1.3
  TOP w0.203: U1.4 R4.1
UNNAMED_4_LINLT3042_I105_ILIM: length 1.4
  TOP w0.203: R19.1 29.02,2.4 U6.5
V_REFN_F: length 12.5
  TOP w0.203: C16.1 v2(42.67,16.38) A1.7 ; U4.16 45.09,9.83 45.77,10.52 v2(45.77,11.18)
  BOTTOM w0.203: v2(42.67,16.38) 44.02,16.38 45.77,14.63 v2(45.77,11.18)
V_REFN_S: length 15.1
  TOP w0.203: A1.6 42.93,17.65 42.76,17.48 v2(42.67,17.48) 42.02,17.48 C16.2 ; U4.17 45.15,9.18 46.33,10.36 v2(46.33,11.89)
  BOTTOM w0.203: v2(42.67,17.48) 44.48,17.48 46.33,15.62 v2(46.33,11.89)
V_REFP_F: length 15.1
  TOP w0.203: A1.1 C15.2 52.35,15.11 v2(52.73,15.49) ; U4.4 48.8,9.18 47.7,10.29 v2(47.7,13.54)
  BOTTOM w0.203: v2(47.7,13.54) 49.66,15.49 v2(52.73,15.49)
V_REFP_S: length 14.9
  TOP w0.203: U4.3 48.72,8.53 47.09,10.16 v2(47.09,12.52) ; C15.1 51.66,16.38 v2(51.03,16.38) A1.2
  BOTTOM w0.203: v2(47.09,12.52) 47.09,14.22 49.25,16.38 v2(51.03,16.38)

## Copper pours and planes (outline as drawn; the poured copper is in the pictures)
3V3 on TOP: 27.64,4.8 25.83,4.8 25.83,4.24 26.62,4.24 26.62,1.91 27.15,1.91 27.15,2.41 26.9,2.67 26.9,4.22 27.64,4.22
3V3 on TOP: 49.07,12.6 51.84,12.6 51.99,12.45 51.99,11.63 52.17,11.46 55.47,11.46 55.7,11.23 55.7,9.12 55.63,9.04 53.47,9.04 53.44,9.07 53.44,10.41 53.29,10.57 51.1,10.57 50.93,10.74 50.93,12.07 50.72,12.27 49.07,12.27
3V3 on BOTTOM: 9.42,6.12 9.42,4.29 9.63,4.09 10.52,4.09 10.77,3.84 10.77,1.37 11.1,1.04 12.42,1.04 12.73,1.35 12.73,3 11.66,4.06 11.66,6.22 11.51,6.38 9.68,6.38
3V3 on L3_PWR: 54.23,11.2 55.65,11.2 55.8,11.05 55.8,7.65 55.22,7.06 50.34,7.06 44.27,0.99 21.08,0.99 21.06,1.01 20.93,1.16 20.83,1.33 20.65,1.44 20.47,1.33 20.37,1.16 20.24,1.01 20.23,0.99 18.54,0.99 18.52,1.01 18.39,1.16 18.29,1.33 18.11,1.44 17.93,1.33 17.83,1.16 17.7,1.01 17.69,0.99 16,0.99 15.98,1.01 15.85,1.16 15.75,1.33 15.57,1.44 15.39,1.33 15.29,1.16 15.16,1.01 15.15,0.99 11.18,0.99 10.67,1.5 10.67,2.9 11.94,4.17 24.31,4.17 24.87,3.61 43.89,3.61 49.63,9.35 53.14,9.35 54.05,10.26 54.05,11.02
AGND on TOP: 0.64,19.68 66.67,19.68 66.67,0.64 0.64,0.64
AGND on BOTTOM: 0.64,19.68 66.67,19.68 66.67,0.64 0.64,0.64 ; 3 cut-outs
AGND on L2_GND: 0.64,19.68 66.67,19.68 66.67,0.64 0.64,0.64 ; 5 cut-outs
VDD on TOP: 41.17,18.72 42.21,18.72 42.32,18.62 42.32,17.98 42.21,17.88 41.5,17.88 41.38,17.75 41.38,15.85 41.78,15.44 45.57,15.44 45.57,14.81 41.78,14.81 41.38,14.4 41.38,13.94 41.1,13.67 39.47,13.67 39.19,13.94 39.19,16.28 39.62,16.71 40.18,16.71 40.82,17.35 40.82,18.36
VDD on TOP: 62.03,12.32 63.09,12.32 63.09,9.5 61.37,7.77 60.48,7.77 60.38,7.87 60.38,9.07 60.48,9.17 61.19,9.17 61.26,9.25 61.26,10.21 61.49,10.44 61.82,10.44 62.03,10.64
VDD on TOP: 32.72,7.98 35.38,7.98 35.69,7.67 35.69,7.32 35.23,6.86 33.3,6.86 33.15,6.71 33.15,5.41 33.71,4.85 33.71,4.27 32.79,4.27 32.79,4.62 32.36,5.05 32.36,7.62
VDD on TOP: 52.81,8.05 54.25,8.05 54.43,7.87 54.43,2.57 53.34,1.47 51.08,1.47 50.8,1.75 50.8,3.43 50.6,3.63 48.36,3.63 48.36,4.27 52.37,4.27 52.63,4.52 52.63,7.87
VDD on TOP: 50.95,10.24 52.1,10.24 52.1,9.68 51.92,9.5 51.92,5.71 51.71,5.51 51.41,5.51 51.23,5.69 51.23,6.71 50.93,7.01 50.93,9.47 50.72,9.68 49.07,9.68 49.07,10.01 50.72,10.01
VDD on L3_PWR: 61.19,14.33 61.19,7.95 57.79,4.55 54.51,4.55 54,4.04 54,2.62 53.67,2.29 52.45,2.29 52.15,2.59 52.15,3.99 51.59,4.55 49.33,4.55 49.15,4.72 49.15,5.33 50.57,6.76 55.35,6.76 56.11,7.52 56.11,10.57 57.1,11.56 57.1,12.93 56.82,13.21 48.01,13.21 41.96,7.16 32.08,7.16 31.67,7.57 29.16,7.57 28.85,7.87 28.85,8.38 29.92,9.45 37.9,9.45 38.76,8.59 40.97,8.59 41.43,9.04 41.43,11.02 39.37,13.08 39.37,14.38 40.23,15.24 52.98,15.24 53.85,16.1 59.41,16.1
VIN on TOP: 10.64,17.98 11.91,17.98 11.91,14.55 12.9,13.56 13.72,13.56 13.72,12.78 12.45,12.78 11.91,12.24 11.91,11.73 12.24,11.4 14.43,11.4 14.73,11.1 16.31,11.1 16.31,10.85 14.73,10.85 14.48,10.59 12.24,10.59 11.91,10.26 11.91,9.83 12.52,9.22 13.72,9.22 13.72,8.46 12.8,8.46 11.91,7.57 11.91,4.01 10.64,4.01 10.64,9.53 10.01,10.16 7.95,10.16 7.95,11.79 10.01,11.79 10.64,12.42
VIN on BOTTOM: 10.77,12.62 10.77,7.42 11.86,6.32 11.86,4.29 14.1,4.29 14.1,7.59 13.31,8.38 13.31,12.62 12.95,12.98 11.13,12.98
VSS on TOP: 32.56,16.18 34.95,16.18 34.95,15.37 33.27,15.37 33.12,15.21 33.12,13.94 33.76,13.31 33.76,12.55 33.66,12.45 33.07,12.45 33.07,13.13 32.38,13.82 32.38,16
VSS on TOP: 38.73,3.07 41.25,3.07 41.5,2.82 41.5,2.11 41.88,1.73 48.03,1.73 48.18,1.57 48.18,1.04 48.34,0.89 50.7,0.89 51.08,1.27 51.87,1.27 51.87,0.64 38.71,0.64 38.46,0.89 38.46,2.79
VSS on TOP: 41.88,19.68 52.38,19.68 53.04,19.02 53.04,17.12 53.47,16.69 54.99,16.69 55.37,16.31 55.37,14.66 54.99,14.27 53.75,14.27 52.48,15.54 52.48,18.24 52.1,18.62 45.92,18.62 45.75,18.8 45.75,19.3 45.62,19.43 43.21,19.43 42.7,18.92 41.73,18.92 41.61,19.05 41.61,19.41
VSS on TOP: 39.73,9.73 41.76,9.73 42.77,8.71 44.86,8.71 44.86,8.38 42.77,8.38 42.55,8.15 41.83,8.15 41.17,7.49 41.17,7.06 40.97,6.86 39.73,6.86 39.37,7.21 39.37,9.37
VSS on L3_PWR: 55.64,19.08 66.14,19.08 66.14,0.97 44.81,0.97 47.98,4.14 51.41,4.14 51.77,3.78 51.77,2.36 52.22,1.91 53.85,1.91 54.38,2.44 54.38,3.86 54.66,4.14 57.94,4.14 61.52,7.72 61.52,14.48 59.56,16.43 53.7,16.43 52.86,15.6 40.11,15.6 39.04,14.53 39.04,12.93 41.05,10.92 41.05,9.25 40.77,8.97 38.91,8.97 38.1,9.78 29.74,9.78 29.03,9.07 28.5,9.07 28.19,9.37 28.19,11.48 28.8,12.09 28.8,18.75 29.13,19.08 38.29,19.08 38.32,19.02 38.51,18.9 38.69,19.02 38.72,19.08 55.21,19.08 55.24,19.02 55.42,18.9 55.61,19.02
IOVCC on TOP: 51.84,12.83 49,12.83 48.87,12.7 48.87,12.45 48.69,12.27 48.23,12.27 48.11,12.4 48.11,13.34 48.26,13.49 51.89,13.49 51.99,13.39 51.99,12.98
IOVCC on BOTTOM: 7.14,2.36 2.77,2.36 2.36,2.77 2.36,4.5 2.82,4.95 6.86,4.95 8,6.1 8.84,6.1 9.09,5.84 9.09,4.32
IOVCC on L3_PWR: 1.3,19.02 28.14,19.02 28.47,18.69 28.47,12.22 27.89,11.63 27.89,9.02 28.52,8.38 28.52,7.67 28.93,7.26 31.5,7.26 31.9,6.86 42.19,6.86 48.13,12.8 56.57,12.8 56.69,12.67 56.69,11.71 56.49,11.51 54.1,11.51 53.72,11.13 53.72,10.36 53.04,9.68 49.5,9.68 43.76,3.94 24.89,3.94 24.28,4.55 11.79,4.55 10.29,3.05 10.29,1.83 9.78,1.32 1.3,1.32 ; 4 cut-outs
NEG_8_VSS on TOP: 25.3,15.6 25.3,14.45 25.04,14.2 22.83,14.2 21.56,12.93 19.81,12.93 18.64,14.1 17.12,14.1 17.12,15.29 21.97,15.29 22.5,15.82 25.07,15.82
NEG_8_VSS on BOTTOM: 22.56,15.82 25.1,15.82 25.37,15.54 25.37,14.58 25.1,14.3 22.43,14.3 18.87,10.74 18.87,4.29 18.69,4.11 18.24,4.11 18.06,4.29 18.06,6.05 18.26,6.25 18.26,11.53
NEG_EX_REF on BOTTOM: 38.94,19.33 42.95,19.33 43.21,19.08 43.21,18.77 42.95,18.52 41.76,18.52 41.17,17.93 41.17,17.02 40.59,16.43 38.96,16.43 38.73,16.66 38.73,19.13
NEG_SET on TOP: 37.59,11.63 37.59,10.19 34.65,10.19 33.71,11.13 33.12,11.13 33.12,11.38 34.44,11.38 34.7,11.63
NEG_VSS on TOP: 30.25,13.92 31.98,13.92 32.84,13.06 32.84,10.82 32.66,10.64 31.11,10.64 30.91,10.85 30.91,11.81 30.73,11.99 30.12,11.99 29.87,12.24 29.87,13.54
NEG_VSS on BOTTOM: 19.43,10.85 28.3,10.85 29.92,12.47 29.92,13.54 30.3,13.92 32.26,13.92 32.66,13.51 32.66,10.82 32.26,10.41 30.45,10.41 29.13,9.09 20.27,9.09 19.89,8.71 19.89,3.89 20.37,3.4 20.37,1.4 20.02,1.04 18.82,1.04 18.41,1.45 18.41,3.51 19.08,4.17 19.08,10.49
PGFB_VNEG on TOP: 30.68,11.43 28.42,11.43 28.42,10.77 29.11,10.77 29.46,10.41 29.46,9.12 30.12,9.12 30.12,11.1 30.68,11.1
PGFB_VPOZ on TOP: 32.79,2.54 33.71,2.54 33.71,2.29 32.92,1.5 32.92,0.64 31.32,0.64 31.32,1.4 31.65,1.4 32.26,2.01 32.61,2.01 32.79,2.18
POZ_8_VDD on TOP: 17.37,8.53 19.58,8.53 19.58,8.13 20.12,7.59 21.84,7.59 22.12,7.87 25.12,7.87 25.3,7.7 25.3,6.5 25.07,6.27 18.21,6.27 17.37,7.11
POZ_8_VDD on BOTTOM: 20.93,7.82 25.07,7.82 25.37,7.52 25.37,6.55 25.07,6.25 21.67,6.25 21.41,5.99 21.41,4.29 21.23,4.11 20.78,4.11 20.6,4.29 20.6,7.49
POZ_EX_REF on BOTTOM: 55.19,16.69 55.19,19.13 54.99,19.33 53.26,19.33 53.06,19.13 53.06,18.62 52.43,17.98 50.88,17.98 50.72,17.83 50.72,17.5 50.88,17.35 52.43,17.35 53.34,16.43 54.94,16.43
POZ_SET on TOP: 32.79,3.05 33.68,3.05 33.76,3.12 37.59,3.12 37.59,1.7 34.7,1.7 34.7,2.06 33.99,2.77 32.79,2.77
POZ_VDD on TOP: 30.61,3.25 30.61,5.41 28.83,5.41 28.83,3.25
POZ_VDD on BOTTOM: 29.24,5.41 29.51,5.41 29.64,5.28 29.64,4.98 28.09,3.43 26.92,3.43 24.54,1.04 21.31,1.04 20.95,1.4 20.95,3.53 21.62,4.19 21.62,5.89 21.77,6.05 22.48,6.05 22.63,5.89 22.63,4.17 22.96,3.84 25.55,3.84 26.52,4.8 28.63,4.8
SENSE_VDD on TOP: 33.35,6.48 33.35,5.51 33.93,4.93 33.93,4.29 33.68,4.04 32.79,4.04 32.79,3.76 34.37,3.76 34.49,3.89 34.49,5.03 34.95,5.49 34.95,6.48
SENSE_VSS on TOP: 33.96,13.41 33.96,12.5 33.71,12.24 33.07,12.24 33.07,12.01 33.81,12.01 34.49,12.7 34.49,13.54 34.98,14.02 34.98,15.01 33.35,15.01 33.35,14.02
UNNAMED_4_CAP_I36_N1 on TOP: 59.77,19.41 61.39,19.41 61.59,19.2 61.59,17.2 61.95,16.84 62.87,16.84 63.07,16.64 63.07,15.11 62.81,14.86 59.82,14.86 59.56,15.11 59.56,19.2
UNNAMED_4_CAP_I36_N1 on BOTTOM: 53.16,15.8 53.37,15.6 54.94,15.6 55.47,15.06 60.71,15.06 60.91,15.27 60.91,16.03 60.71,16.23 53.37,16.23 53.16,16.03
UNNAMED_4_CAP_I132_N2 on TOP: 31.67,8.84 35.79,8.84 36.55,8.08 36.55,5.16 37.59,4.11 37.59,3.48 34.7,3.48 34.7,4.93 35.18,5.41 35.18,6.5 35.89,7.21 35.89,7.8 35.51,8.18 32.61,8.18 32.16,7.72 32.16,6.86 30.56,6.86 30.56,7.72
UNNAMED_4_CAP_I152_N1 on TOP: 13.51,17.98 14.71,17.98 14.71,15.82 16.48,15.82 16.48,12.4 16.31,12.22 16.31,11.84 15.16,11.84 14.96,12.04 14.96,14 14.73,14.22 13.51,14.22
UNNAMED_4_CAP_I152_N2 on TOP: 15.34,17.86 15.34,16.38 17.07,16.38 17.4,16.71 22.71,16.71 22.71,18.19 15.67,18.19
UNNAMED_4_CAP_I197_N2 on TOP: 36.3,16.61 36.3,13.92 37.59,12.62 37.59,11.99 34.7,11.99 34.7,13.46 35.2,13.97 35.2,16.33 35.08,16.46 32.54,16.46 32.16,16.08 32.16,15.37 30.56,15.37 30.56,16.23 31.67,17.35 35.56,17.35
UNNAMED_4_DIOSCHOTTKY_I78_P on TOP: 13.5,4.01 15.11,4.01 16.48,5.38 16.48,9.54 16.31,9.72 16.31,10.11 15.16,10.11 14.96,9.91 14.96,8.03 14.73,7.8 13.5,7.8
UNNAMED_4_LINLTC6655V2_I268_SHD on TOP: 61.01,12.32 61.8,12.32 61.8,10.79 61.47,10.79 61.04,10.36 61.04,9.42 60.38,9.42 60.38,11.68
V_EXT on BOTTOM: 14.5,6.07 15.16,6.07 15.34,5.89 15.34,1.5 14.88,1.04 13.74,1.04 13.34,1.45 13.34,3.02 14.3,3.99 14.3,5.87

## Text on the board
Ref Des/Silkscreen Bottom: GND | VSS | VDD | NEG | EXT | REF | EVAL-CN0531-PMDZ | POZ | EXT BUFF | EXT IOVDD | LDAC | EXT 3V3 | CLR | EXT VIN | RESET
Ref Des/Assembly Top: WIRE ENTRY | A | C
Ref Des/Silkscreen Top: A | GND | C | VSS | VDD | RST | LD | CLR | 3V3 | VIN | BUFF | VOUT
PAGE_OUTLINE: 09AUG19 | B | AS PER ECR-092956 | 11SEP20 | M.SUCIU | EVAL-CN0531-PMDZ
DIMENSION: - | (REF) | NON PLATED: +/- 2 MILS | DIA MAX
User.12: 1 | A. P6 | B. P7 | C. P9 | D. P10 | E. P11 | F. P12 | G. P13 | OF THE COMPONENTS BELOW: | 5.    ASSEMBLY VENDOR MUST SOLDER SHORT ON DEFAULT POSISTION PIN 1 & 2
User.17: 08-      -07 | L2 GND
User.18: L3 PWR | 08-      -08
User.45: FIGURE | SIZE | 10.0 | 15.0 | 45.0 | 47.0 | PLATED | NON-PLATED | DRILL CHART: TOP to BOTTOM | ALL UNITS ARE IN MILS | QTY | 142 | 8 | 25 | 3 | TOLERANCE/NOTES
